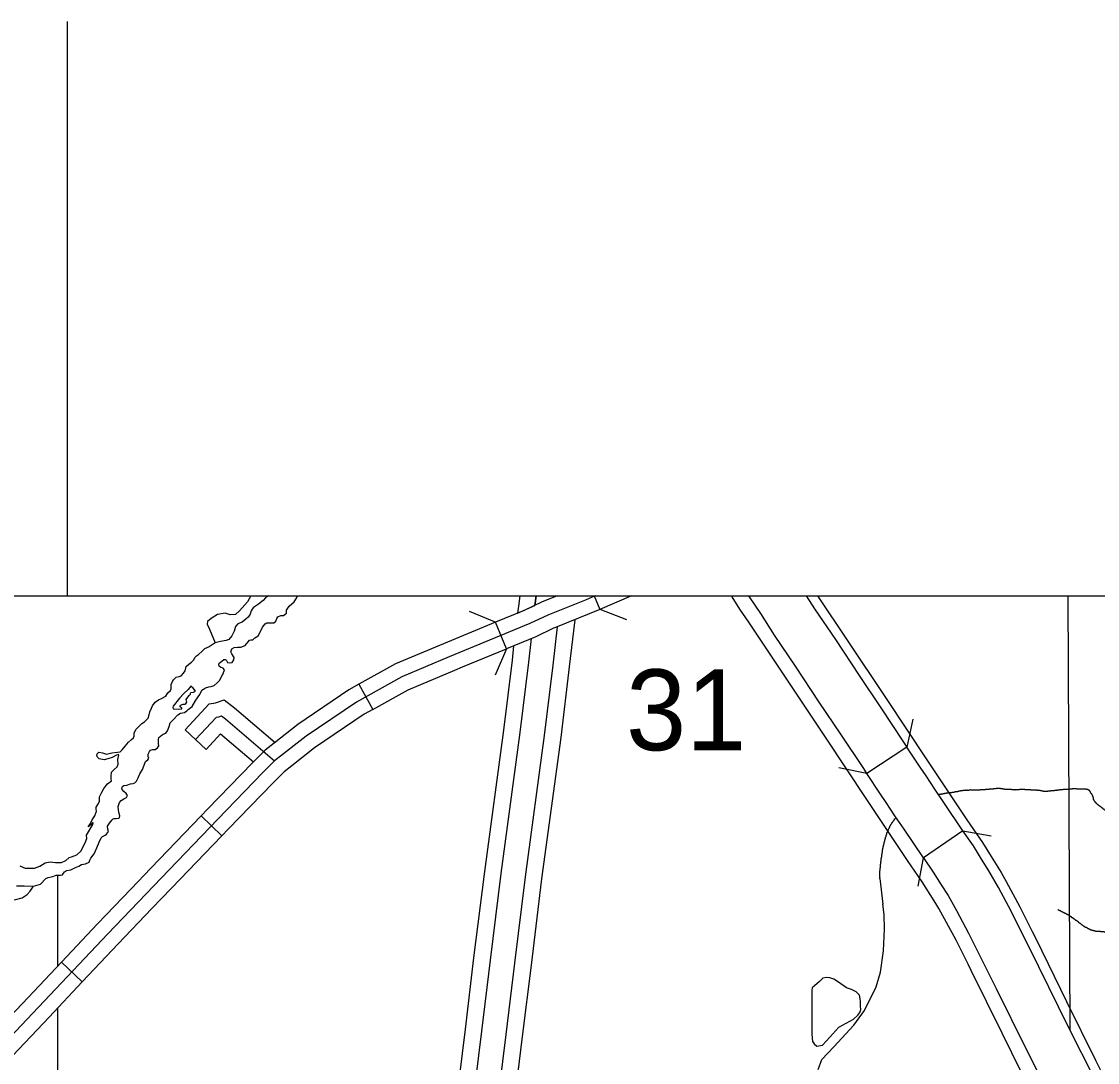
# Model space of a CAD drawing. Extents: x 813775 to 1157140, y 1757555 to 1979907.
# Drawn here: x 985663 to 996904, y 1875834 to 1886709 of the extents above; entities that cross this region are included whole.
import ezdxf

# ---------------------------------------------------------------- set-up
doc = ezdxf.new("R2010")
doc.units = 0
for name, color, linetype in [('Level 15', 7, 'Continuous'), ('Level 19', 7, 'Continuous'), ('Level 31', 7, 'Continuous'), ('Level 32', 7, 'Continuous'), ('Level 35', 7, 'Continuous'), ('Level 37', 7, 'Continuous'), ('Level 38', 7, 'Continuous'), ('Level 4', 7, 'Continuous'), ('Level 5', 7, 'Continuous'), ('Level 6', 7, 'Continuous'), ('Level 9', 7, 'Continuous'), ('R_Dimension', 7, 'Continuous'), ('R_Draft', 7, 'Continuous')]:
    doc.layers.add(name, color=color, linetype=linetype)

msp = doc.modelspace()

# ---------------------------------------------------------------- linework, layer by layer
at = {"layer": 'Level 15'}
for points in [[(994496, 1878853), (994462, 1878905), (994224, 1879263), (993997, 1879599), (993751, 1879974), (993531, 1880299), (993387, 1880525), (993267, 1880698), (993260, 1880709)], [(993862, 1880709), (993949, 1880574), (994167, 1880252), (994414, 1879876), (994640, 1879541), (994879, 1879181), (994913, 1879128)], [(994913, 1879128), (994496, 1878853)], [(995499, 1878255), (995299, 1878552), (995204, 1878690), (995113, 1878830), (995052, 1878918), (994913, 1879128)], [(995087, 1877972), (994885, 1878271), (994788, 1878412), (994698, 1878551), (994639, 1878637), (994496, 1878853)], [(995499, 1878255), (995087, 1877972)], [(996876, 1875661), (996602, 1876202), (996293, 1876832), (996001, 1877414), (995872, 1877661), (995770, 1877838), (995694, 1877957), (995608, 1878096), (995499, 1878255)], [(995087, 1877972), (995189, 1877823), (995271, 1877690), (995343, 1877578), (995433, 1877421), (995556, 1877186), (995845, 1876609), (996155, 1875979), (996430, 1875435)]]:
    msp.add_lwpolyline(points, dxfattribs=at)
at = {"layer": 'Level 19'}
for points in [[(990869, 1880709), (990855, 1880603), (990846, 1880528), (991027, 1880610)], [(991041, 1880709), (991027, 1880610)], [(991027, 1880610), (991041, 1880709)], [(991442, 1880460), (991386, 1879966), (991296, 1879228), (991097, 1877752), (990986, 1876852), (990895, 1876107), (990645, 1874074)], [(990477, 1874095), (990726, 1876128), (990817, 1876873), (990928, 1877774), (991127, 1879250), (991218, 1879986), (991263, 1880387)], [(990987, 1880262), (990959, 1880017), (990869, 1879283), (990671, 1877807), (990559, 1876905), (990468, 1876161), (990219, 1874128)], [(990050, 1874150), (990300, 1876183), (990390, 1876926), (990502, 1877829), (990701, 1879305), (990791, 1880037), (990808, 1880188)]]:
    msp.add_lwpolyline(points, dxfattribs=at)
at = {"layer": 'Level 31'}
for p, q in [((989187, 1879785), (989333, 1879523)), ((987755, 1878203), (987539, 1878411)), ((986079, 1876882), (986297, 1876677))]:
    msp.add_line(p, q, dxfattribs=at)
for points in [[(991260, 1880709), (991129, 1880657)], [(991645, 1880709), (991706, 1880567)], [(992036, 1880709), (991706, 1880567)], [(991129, 1880657), (991101, 1880646), (990913, 1880556), (990616, 1880433)], [(991706, 1880567), (991241, 1880378)], [(990731, 1880156), (990616, 1880433), (990156, 1880243)], [(991241, 1880378), (991221, 1880371), (991035, 1880282), (990731, 1880156)], [(990156, 1880243), (990073, 1880209), (989570, 1879998), (989187, 1879785)], [(990271, 1879966), (990731, 1880156)], [(989333, 1879523), (989702, 1879728), (990189, 1879932), (990271, 1879966)], [(989187, 1879785), (989084, 1879727), (988548, 1879364), (988301, 1879170)], [(989333, 1879523), (989242, 1879472), (988725, 1879121), (988487, 1878934)], [(988301, 1879170), (988207, 1879096), (988075, 1878964), (987606, 1878481), (987539, 1878411)], [(988487, 1878934), (988406, 1878871), (988289, 1878753), (987821, 1878272), (987755, 1878203)], [(987539, 1878411), (987012, 1877864), (986807, 1877649)], [(987023, 1877442), (987229, 1877656), (987755, 1878203)], [(986807, 1877649), (986455, 1877282), (986079, 1876882)], [(986297, 1876677), (986673, 1877075), (987023, 1877442)], [(986079, 1876882), (985732, 1876514), (985354, 1876116)], [(986297, 1876677), (985950, 1876308), (985571, 1875909)]]:
    msp.add_lwpolyline(points, dxfattribs=at)
at = {"layer": 'Level 32'}
msp.add_line((987592, 1879105), (987372, 1879309), dxfattribs=at)
for points in [[(991656, 1880709), (991563, 1880669), (991161, 1880508), (990974, 1880419), (990131, 1880071), (989636, 1879863), (989163, 1879600), (988637, 1879242), (988307, 1878984), (988182, 1878859), (987714, 1878376), (987120, 1877760), (986564, 1877179)], [(987372, 1879309), (987623, 1879581), (987689, 1879592), (987781, 1879623), (987887, 1879540), (988311, 1879177)], [(987482, 1879207), (987698, 1879441), (987725, 1879446), (987752, 1879455), (987793, 1879423), (988307, 1878984)], [(987592, 1879105), (987743, 1879269), (988086, 1878975)], [(986564, 1877179), (985841, 1876411), (985123, 1875656), (984450, 1874962)]]:
    msp.add_lwpolyline(points, dxfattribs=at)
at = {"layer": 'Level 35'}
msp.add_line((994629, 1877756), (994663, 1877490), dxfattribs=at)
for points in [[(988059, 1880709), (988022, 1880646), (987941, 1880554), (987899, 1880515), (987844, 1880510), (987790, 1880528), (987711, 1880513), (987643, 1880473), (987607, 1880440), (987602, 1880413), (987625, 1880361), (987687, 1880220)], [(985752, 1877624), (985787, 1877675)], [(985588, 1877532), (985671, 1877556), (985721, 1877590), (985752, 1877624)], [(993986, 1875760), (994026, 1875865), (994151, 1875998), (994358, 1876226), (994469, 1876378), (994591, 1876625), (994637, 1876777), (994668, 1877000), (994679, 1877229), (994676, 1877377), (994663, 1877491)], [(994283, 1876614), (994198, 1876675), (994151, 1876705), (994109, 1876719), (994072, 1876721), (994034, 1876716), (994000, 1876680), (993949, 1876636), (993925, 1876615), (993920, 1876586), (993919, 1876451), (993920, 1876276)], [(993920, 1876276), (993919, 1876130), (993927, 1876055), (993944, 1876028), (993971, 1876005), (994032, 1876016), (994107, 1876098), (994202, 1876205), (994354, 1876287), (994401, 1876328), (994423, 1876355), (994433, 1876388), (994429, 1876424), (994427, 1876472), (994426, 1876500), (994418, 1876536), (994382, 1876572), (994336, 1876597), (994283, 1876614)]]:
    msp.add_lwpolyline(points, dxfattribs=at)
for points in [[(995243, 1878634), (995248, 1878636), (995254, 1878636), (995260, 1878639), (995265, 1878639), (995271, 1878639), (995276, 1878642), (995282, 1878642), (995287, 1878642), (995293, 1878645), (995299, 1878645), (995304, 1878645), (995310, 1878647), (995315, 1878647), (995321, 1878647), (995326, 1878650), (995332, 1878650), (995338, 1878653), (995343, 1878653), (995349, 1878656), (995354, 1878656), (995360, 1878656), (995366, 1878656)], [(995366, 1878656), (995371, 1878656), (995377, 1878656), (995382, 1878656), (995388, 1878659), (995393, 1878659), (995399, 1878659), (995405, 1878659), (995410, 1878661), (995416, 1878661), (995421, 1878664), (995427, 1878664), (995432, 1878664), (995438, 1878664), (995444, 1878667), (995449, 1878670), (995455, 1878670), (995460, 1878672), (995466, 1878672), (995472, 1878672), (995477, 1878675), (995483, 1878675), (995488, 1878675), (995494, 1878675), (995499, 1878678), (995505, 1878678), (995511, 1878678), (995516, 1878678), (995522, 1878681), (995527, 1878681), (995533, 1878681), (995538, 1878681), (995544, 1878681), (995550, 1878681), (995555, 1878681), (995564, 1878681), (995569, 1878684), (995578, 1878684), (995583, 1878684), (995589, 1878684), (995594, 1878684), (995600, 1878684), (995605, 1878684), (995611, 1878684), (995617, 1878684), (995622, 1878684), (995628, 1878684), (995633, 1878684), (995642, 1878684), (995647, 1878684), (995653, 1878684), (995658, 1878684), (995664, 1878684), (995672, 1878684), (995678, 1878684), (995686, 1878686), (995692, 1878686), (995697, 1878686), (995703, 1878686), (995709, 1878686), (995714, 1878686), (995720, 1878686), (995725, 1878686), (995731, 1878686), (995737, 1878689), (995742, 1878689), (995748, 1878689), (995753, 1878689), (995759, 1878689), (995764, 1878689), (995770, 1878689), (995776, 1878692), (995781, 1878692), (995787, 1878692), (995792, 1878692), (995798, 1878692), (995803, 1878692), (995809, 1878692), (995815, 1878692), (995820, 1878695), (995826, 1878695), (995831, 1878695), (995837, 1878698), (995845, 1878698), (995851, 1878700), (995856, 1878700), (995862, 1878700), (995868, 1878700), (995873, 1878700), (995879, 1878700), (995884, 1878700)], [(995884, 1878700), (995890, 1878698), (995896, 1878698), (995901, 1878698), (995907, 1878695), (995912, 1878695), (995918, 1878692), (995923, 1878692), (995929, 1878692), (995935, 1878689), (995940, 1878689), (995946, 1878689), (995951, 1878689), (995957, 1878689), (995962, 1878689), (995968, 1878689), (995974, 1878689), (995979, 1878689), (995985, 1878689), (995990, 1878689), (995996, 1878689), (996002, 1878689), (996007, 1878686), (996013, 1878686), (996018, 1878686), (996024, 1878686), (996029, 1878686), (996035, 1878686), (996041, 1878684), (996046, 1878684), (996052, 1878686), (996057, 1878686), (996063, 1878686), (996068, 1878686), (996074, 1878686), (996080, 1878686), (996085, 1878686), (996091, 1878689), (996096, 1878689), (996102, 1878689), (996108, 1878689), (996113, 1878689), (996119, 1878689), (996124, 1878689), (996130, 1878689), (996135, 1878689), (996141, 1878689), (996147, 1878686), (996152, 1878686), (996158, 1878686), (996163, 1878686), (996169, 1878686), (996174, 1878686), (996180, 1878686), (996186, 1878686), (996191, 1878686), (996197, 1878686), (996202, 1878686), (996208, 1878684), (996214, 1878684), (996219, 1878684), (996225, 1878684), (996230, 1878684), (996236, 1878684), (996241, 1878684), (996247, 1878684), (996253, 1878684), (996258, 1878684), (996264, 1878684), (996269, 1878681), (996275, 1878681), (996280, 1878681), (996286, 1878678), (996292, 1878678), (996297, 1878678), (996303, 1878678), (996308, 1878675), (996314, 1878675), (996320, 1878675), (996325, 1878675), (996331, 1878672), (996336, 1878670), (996342, 1878670), (996347, 1878670), (996353, 1878670), (996359, 1878670), (996364, 1878670), (996370, 1878670), (996375, 1878670), (996381, 1878670), (996387, 1878670)], [(996387, 1878670), (996392, 1878672), (996398, 1878672), (996403, 1878672), (996409, 1878672), (996414, 1878672), (996420, 1878675), (996426, 1878675), (996431, 1878675), (996437, 1878675), (996442, 1878675), (996448, 1878675), (996453, 1878675), (996459, 1878678), (996465, 1878678), (996470, 1878678), (996476, 1878681), (996481, 1878681), (996487, 1878681), (996493, 1878684), (996498, 1878684), (996504, 1878684), (996509, 1878684), (996515, 1878686), (996520, 1878686), (996526, 1878686), (996532, 1878686), (996537, 1878686), (996543, 1878686), (996548, 1878689), (996554, 1878689), (996559, 1878689), (996565, 1878689), (996571, 1878689), (996576, 1878689), (996582, 1878689), (996587, 1878689), (996593, 1878689), (996599, 1878689), (996604, 1878689), (996610, 1878689), (996615, 1878692), (996621, 1878692), (996626, 1878692), (996632, 1878692), (996638, 1878692), (996643, 1878695), (996649, 1878695), (996654, 1878695), (996660, 1878695), (996665, 1878695), (996671, 1878695), (996677, 1878695), (996682, 1878695), (996688, 1878692), (996693, 1878692), (996699, 1878692), (996705, 1878692), (996710, 1878692), (996716, 1878692), (996721, 1878692), (996727, 1878692), (996732, 1878692), (996738, 1878692), (996744, 1878692), (996749, 1878692), (996755, 1878692), (996760, 1878692), (996766, 1878692), (996771, 1878692), (996777, 1878692), (996783, 1878692), (996788, 1878689), (996794, 1878689), (996799, 1878689), (996805, 1878686), (996811, 1878684), (996816, 1878681), (996819, 1878675), (996824, 1878672), (996824, 1878667), (996827, 1878661), (996830, 1878656), (996833, 1878650), (996838, 1878647), (996841, 1878642), (996844, 1878636), (996847, 1878631), (996850, 1878625), (996852, 1878619), (996855, 1878614)], [(996855, 1878614), (996855, 1878608), (996858, 1878603), (996858, 1878597), (996858, 1878592), (996861, 1878586), (996864, 1878580), (996866, 1878575), (996869, 1878569), (996872, 1878564), (996877, 1878561), (996880, 1878555), (996886, 1878550), (996889, 1878544), (996894, 1878541), (996897, 1878536), (996903, 1878533), (996908, 1878530), (996911, 1878525), (996917, 1878522), (996922, 1878519), (996928, 1878513), (996933, 1878511), (996939, 1878505), (996944, 1878502), (996950, 1878497), (996956, 1878494), (996958, 1878488), (996964, 1878485), (996970, 1878483), (996975, 1878477), (996981, 1878474), (996986, 1878469), (996992, 1878466), (996997, 1878460), (997003, 1878458), (997009, 1878452), (997014, 1878449), (997020, 1878444), (997025, 1878441), (997031, 1878441), (997036, 1878438), (997042, 1878438), (997048, 1878435), (997053, 1878432), (997059, 1878430), (997064, 1878427), (997070, 1878424), (997076, 1878418), (997081, 1878416), (997087, 1878413), (997092, 1878413), (997098, 1878410), (997103, 1878410), (997109, 1878410), (997115, 1878410), (997120, 1878407), (997126, 1878407), (997131, 1878407), (997137, 1878405), (997141, 1878402)], [(994640, 1877911), (994640, 1877919), (994640, 1877924), (994640, 1877930), (994643, 1877938), (994643, 1877947), (994646, 1877955), (994646, 1877964), (994649, 1877972), (994649, 1877980), (994651, 1877989), (994651, 1877997), (994651, 1878003), (994654, 1878011), (994654, 1878017), (994654, 1878022), (994657, 1878031), (994657, 1878036), (994657, 1878042), (994660, 1878050), (994660, 1878058), (994663, 1878067), (994663, 1878072), (994665, 1878078), (994665, 1878084), (994665, 1878089), (994668, 1878095), (994668, 1878100), (994671, 1878106), (994671, 1878111), (994674, 1878117), (994674, 1878123), (994676, 1878131), (994679, 1878139), (994682, 1878148), (994682, 1878156), (994685, 1878162), (994685, 1878167), (994688, 1878173), (994690, 1878181), (994690, 1878187), (994693, 1878192), (994696, 1878198), (994696, 1878204), (994699, 1878212), (994702, 1878220), (994704, 1878226), (994704, 1878231), (994707, 1878237), (994710, 1878243), (994713, 1878248), (994716, 1878254), (994718, 1878262), (994721, 1878268), (994724, 1878273), (994727, 1878279), (994729, 1878285), (994732, 1878290), (994735, 1878296), (994735, 1878301), (994738, 1878307), (994743, 1878315), (994746, 1878321), (994752, 1878326), (994755, 1878332), (994757, 1878338), (994760, 1878343), (994766, 1878346), (994769, 1878352), (994771, 1878357), (994777, 1878363), (994780, 1878368), (994782, 1878374), (994785, 1878379), (994791, 1878382), (994794, 1878388), (994799, 1878393)], [(994629, 1877756), (994629, 1877760), (994629, 1877765), (994632, 1877771), (994632, 1877777), (994632, 1877782), (994632, 1877788), (994632, 1877796), (994632, 1877804), (994632, 1877810), (994632, 1877818), (994632, 1877824), (994632, 1877832), (994632, 1877838), (994635, 1877846), (994635, 1877855), (994635, 1877860), (994635, 1877869), (994637, 1877877), (994637, 1877885), (994637, 1877894), (994637, 1877902), (994640, 1877911)], [(996791, 1877244), (996785, 1877246), (996780, 1877246), (996774, 1877249), (996769, 1877255), (996763, 1877257), (996758, 1877260), (996752, 1877266), (996746, 1877269), (996741, 1877271), (996738, 1877277), (996732, 1877280), (996727, 1877285), (996721, 1877288), (996716, 1877291), (996710, 1877294), (996707, 1877299), (996702, 1877305), (996696, 1877308), (996691, 1877313), (996685, 1877316), (996679, 1877319), (996674, 1877324), (996668, 1877327), (996663, 1877330), (996660, 1877336), (996654, 1877338), (996649, 1877341), (996643, 1877347), (996638, 1877347), (996635, 1877352), (996629, 1877355), (996624, 1877358), (996618, 1877364), (996612, 1877366), (996607, 1877372), (996601, 1877375), (996596, 1877377), (996590, 1877380), (996585, 1877383), (996579, 1877386), (996573, 1877391), (996568, 1877391), (996562, 1877394), (996557, 1877397), (996551, 1877400), (996546, 1877403), (996540, 1877405), (996534, 1877408), (996529, 1877411), (996523, 1877414), (996518, 1877417), (996512, 1877419), (996506, 1877422), (996501, 1877425), (996495, 1877428), (996490, 1877430)], [(997290, 1877104), (997285, 1877104), (997279, 1877107), (997274, 1877107), (997268, 1877110), (997262, 1877112), (997257, 1877115), (997251, 1877118), (997246, 1877121), (997240, 1877123), (997235, 1877126), (997229, 1877126), (997223, 1877129), (997218, 1877132), (997212, 1877132), (997207, 1877132), (997201, 1877135), (997195, 1877137), (997190, 1877137), (997184, 1877137), (997179, 1877140), (997173, 1877140), (997168, 1877140), (997162, 1877140), (997156, 1877140), (997151, 1877140), (997145, 1877140), (997140, 1877140), (997134, 1877140), (997129, 1877140), (997123, 1877140), (997117, 1877140), (997112, 1877143), (997106, 1877143), (997101, 1877146), (997095, 1877146), (997089, 1877149), (997084, 1877149), (997078, 1877151), (997073, 1877154), (997067, 1877157), (997062, 1877157), (997059, 1877163), (997053, 1877165), (997048, 1877168), (997042, 1877171), (997036, 1877174), (997031, 1877177), (997025, 1877182), (997020, 1877182), (997014, 1877185), (997009, 1877185), (997003, 1877188), (996997, 1877190), (996992, 1877193), (996986, 1877196), (996981, 1877196), (996975, 1877199), (996970, 1877199), (996964, 1877199), (996958, 1877199), (996953, 1877199), (996947, 1877199), (996942, 1877199), (996936, 1877202), (996930, 1877202), (996925, 1877202), (996919, 1877202), (996914, 1877202), (996908, 1877202), (996903, 1877202), (996897, 1877202), (996891, 1877204), (996886, 1877204), (996880, 1877207), (996875, 1877207), (996869, 1877210), (996864, 1877210), (996858, 1877213), (996852, 1877213), (996847, 1877216), (996841, 1877216), (996836, 1877218), (996830, 1877221), (996824, 1877224), (996819, 1877227), (996813, 1877230), (996808, 1877232), (996802, 1877235), (996797, 1877241), (996791, 1877244)]]:
    msp.add_spline(points, degree=3, dxfattribs=at)
at = {"layer": 'Level 37'}
for points in [[(994974, 1879422), (994914, 1879128)], [(994496, 1878853), (994203, 1878914)], [(995497, 1878256), (995792, 1878202)], [(995031, 1877677), (995085, 1877972)]]:
    msp.add_lwpolyline(points, dxfattribs=at)
at = {"layer": 'Level 38'}
for points in [[(991988, 1880459), (991709, 1880568)], [(990340, 1880550), (990617, 1880433)], [(990730, 1880156), (990613, 1879879)]]:
    msp.add_lwpolyline(points, dxfattribs=at)
at = {"layer": 'Level 4'}
for points in [[(986037, 1877792), (986038, 1876839)], [(986039, 1876402), (986040, 1875566)]]:
    msp.add_lwpolyline(points, dxfattribs=at)
at = {"layer": 'Level 5'}
msp.add_lwpolyline([(996593, 1880709), (996617, 1876173)], dxfattribs=at)
at = {"layer": 'Level 6'}
for points in [[(996213, 1875525), (995907, 1876141), (995586, 1876797), (995552, 1876862), (995427, 1877112), (995248, 1877443), (995217, 1877494), (995156, 1877589), (995073, 1877723), (994919, 1877946), (994487, 1878591), (994071, 1879221), (993664, 1879828), (993261, 1880434), (993168, 1880571), (993089, 1880700), (993084, 1880709)], [(993980, 1880709), (994288, 1880245), (994696, 1879637), (995113, 1879007), (995541, 1878368), (995702, 1878134), (995792, 1877988), (995899, 1877819), (995950, 1877724), (996093, 1877459), (996221, 1877204), (996260, 1877128), (996581, 1876473), (996885, 1875860), (997049, 1875532)]]:
    msp.add_lwpolyline(points, dxfattribs=at)
at = {"layer": 'Level 9'}
for points in [[(988244, 1880709), (988213, 1880688), (988187, 1880659), (988140, 1880621), (988088, 1880586), (988072, 1880570), (988063, 1880552), (988053, 1880518), (988031, 1880486), (988006, 1880465), (987967, 1880435), (987921, 1880416), (987898, 1880389), (987885, 1880342), (987859, 1880292), (987830, 1880253), (987801, 1880244), (987741, 1880231), (987687, 1880220), (987622, 1880175), (987574, 1880154)], [(988181, 1880381), (988207, 1880416), (988226, 1880428), (988272, 1880427), (988299, 1880429), (988318, 1880445), (988329, 1880471), (988341, 1880489), (988371, 1880503), (988401, 1880505), (988431, 1880527), (988431, 1880561), (988460, 1880600), (988511, 1880647), (988535, 1880685), (988546, 1880709)], [(987765, 1879888), (987770, 1879898), (987785, 1879937), (987769, 1879954), (987746, 1879960), (987727, 1879976), (987724, 1879992), (987727, 1880007), (987754, 1880028), (987776, 1880044), (987793, 1880044), (987805, 1880033), (987815, 1880014), (987831, 1880008), (987864, 1880012), (987881, 1880040), (987885, 1880065), (987860, 1880102), (987848, 1880126), (987859, 1880155), (987886, 1880170), (987919, 1880172), (987955, 1880172), (987999, 1880191), (988044, 1880246), (988057, 1880250), (988078, 1880251), (988101, 1880270), (988136, 1880293), (988153, 1880322), (988181, 1880381)], [(987371, 1879927), (987384, 1879971), (987410, 1879997), (987440, 1880018), (987463, 1880040), (987475, 1880065), (987492, 1880082), (987513, 1880095), (987551, 1880132), (987574, 1880154)], [(987032, 1879560), (987058, 1879599), (987092, 1879623), (987126, 1879637), (987169, 1879661), (987192, 1879697), (987218, 1879722), (987225, 1879739), (987225, 1879756), (987225, 1879783), (987240, 1879813), (987251, 1879833), (987280, 1879860), (987310, 1879867), (987329, 1879875), (987354, 1879900), (987371, 1879927)], [(987325, 1879482), (987364, 1879492), (987391, 1879509), (987404, 1879522), (987445, 1879555), (987484, 1879620), (987525, 1879680), (987547, 1879723), (987564, 1879736), (987586, 1879748), (987620, 1879758), (987645, 1879761), (987675, 1879774), (987706, 1879800), (987732, 1879824), (987767, 1879892)], [(987376, 1879578), (987390, 1879599), (987388, 1879613), (987384, 1879627), (987401, 1879650), (987415, 1879668), (987427, 1879681), (987427, 1879694), (987433, 1879698), (987461, 1879704), (987480, 1879715), (987456, 1879744), (987433, 1879766), (987402, 1879732), (987354, 1879685), (987312, 1879640), (987247, 1879557), (987242, 1879543), (987248, 1879530), (987307, 1879527), (987337, 1879530), (987336, 1879536), (987320, 1879551), (987320, 1879560), (987325, 1879568), (987350, 1879576), (987373, 1879578)], [(986428, 1878410), (986445, 1878461), (986443, 1878480), (986443, 1878502), (986467, 1878540), (986476, 1878563), (986476, 1878587), (986478, 1878610), (986503, 1878660), (986523, 1878696), (986560, 1878744), (986590, 1878765), (986603, 1878777), (986600, 1878799), (986598, 1878825), (986604, 1878867), (986632, 1878895), (986662, 1878923), (986672, 1878950), (986669, 1879001), (986677, 1879030), (986681, 1879044), (986680, 1879048), (986672, 1879052), (986655, 1879044), (986609, 1879022), (986566, 1879006), (986527, 1878997), (986475, 1879008), (986456, 1879023), (986450, 1879040), (986453, 1879058), (986470, 1879077), (986508, 1879069), (986552, 1879057), (986606, 1879068), (986664, 1879075), (986694, 1879081), (986714, 1879100), (986744, 1879139), (986779, 1879180), (986810, 1879210), (986834, 1879225), (986839, 1879247), (986839, 1879278), (986859, 1879315), (986889, 1879345), (986920, 1879376), (986946, 1879392), (986985, 1879431), (986997, 1879466), (987002, 1879496), (987020, 1879537), (987032, 1879560)], [(986688, 1878410), (986682, 1878436), (986676, 1878472), (986672, 1878507), (986686, 1878550), (986705, 1878573), (986731, 1878590), (986761, 1878603), (986769, 1878622), (986756, 1878643), (986732, 1878665), (986715, 1878687), (986712, 1878704), (986719, 1878718), (986731, 1878729), (986763, 1878730), (986801, 1878747), (986829, 1878750), (986847, 1878755), (986865, 1878773), (986881, 1878808), (986900, 1878849), (986926, 1878896), (986943, 1878939), (986959, 1878979), (986981, 1878997), (986992, 1879014), (986986, 1879032), (986986, 1879056), (986999, 1879084), (987009, 1879097), (987035, 1879104), (987059, 1879105), (987085, 1879123), (987096, 1879144), (987093, 1879168), (987092, 1879210), (987098, 1879228), (987132, 1879259), (987142, 1879266), (987170, 1879276), (987187, 1879300), (987206, 1879343), (987217, 1879384), (987252, 1879418), (987294, 1879467), (987325, 1879482)], [(985609, 1877680), (985691, 1877679), (985787, 1877675), (985862, 1877699), (985916, 1877756), (985940, 1877768), (985989, 1877778), (986025, 1877791), (986070, 1877793), (986090, 1877796), (986102, 1877811), (986113, 1877826), (986133, 1877840), (986179, 1877847), (986226, 1877870), (986263, 1877884), (986289, 1877902), (986331, 1877911), (986370, 1877928), (986378, 1877948), (986385, 1877969), (986420, 1878014), (986451, 1878076), (986473, 1878136), (986495, 1878183), (986509, 1878196), (986535, 1878210), (986552, 1878221), (986571, 1878247), (986565, 1878273), (986561, 1878302), (986582, 1878336), (986610, 1878369), (986619, 1878380), (986632, 1878382), (986651, 1878382), (986681, 1878386), (986687, 1878394), (986688, 1878410)], [(985645, 1877888), (985701, 1877864), (985761, 1877863), (985799, 1877866), (985855, 1877887), (985910, 1877919), (985961, 1877932), (986016, 1877924), (986081, 1877923), (986125, 1877944), (986160, 1877977), (986185, 1877982), (986242, 1878004), (986283, 1878042), (986329, 1878128), (986344, 1878174), (986343, 1878208), (986409, 1878321), (986411, 1878338), (986403, 1878337), (986391, 1878321), (986360, 1878295), (986383, 1878330), (986400, 1878369), (986428, 1878410)]]:
    msp.add_lwpolyline(points, dxfattribs=at)
at = {"layer": 'R_Dimension'}
msp.add_line((986141, 1886709), (986141, 1880709), dxfattribs=at)
at = {"layer": 'R_Draft'}
msp.add_lwpolyline([(912532, 1880709), (1062535, 1880709), (1062535, 1798155), (912532, 1798155)], close=True, dxfattribs=at)

# ---------------------------------------------------------------- texts
at = {"layer": 'Level 5'}
msp.add_text('31', height=844.8, dxfattribs=at).set_placement((991979, 1879096))

doc.saveas('drawing.dxf')
